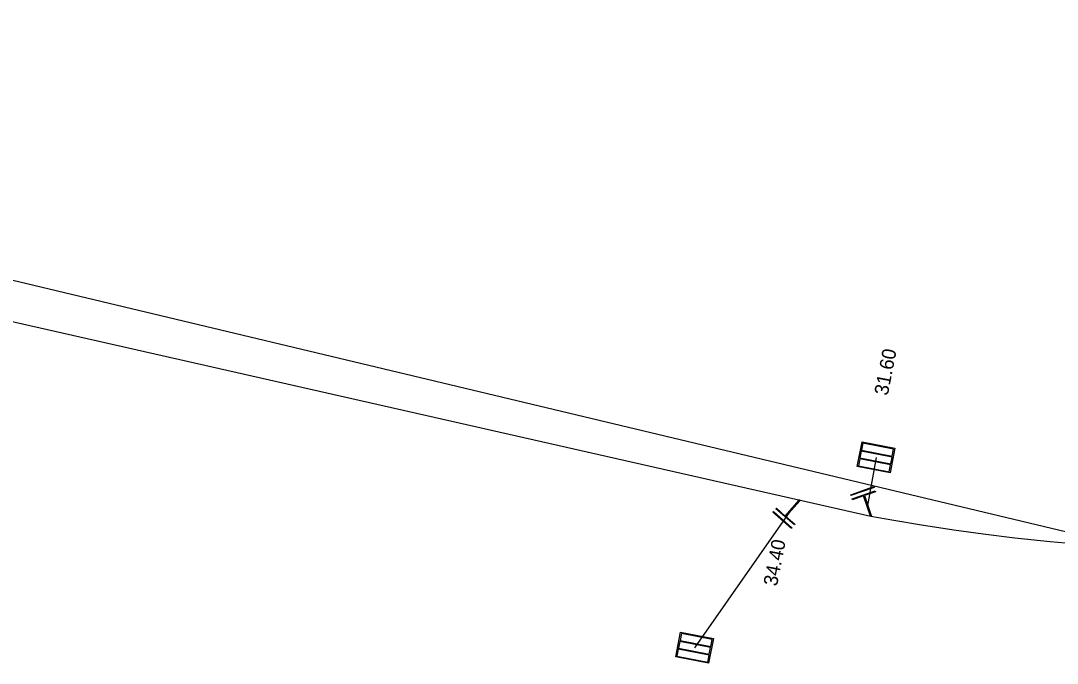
# Model space of a CAD drawing. Extents: x -817726 to -817387, y -1067947 to -1067694.
# Drawn here: x -817640.17 to -817603.04, y -1067814.67 to -1067791.65 of the extents above; entities that cross this region are included whole.
import ezdxf

# ---------------------------------------------------------------- set-up
doc = ezdxf.new("R2010")
doc.units = 0
doc.layers.add('Default', color=7, linetype='Continuous')
doc.layers.add('Level 0', color=7, linetype='Continuous')

msp = doc.modelspace()

# ---------------------------------------------------------------- linework, layer by layer
at = {"layer": 'Default'}
for points in [[(-817610.031, -1067806.741), (-817608.853, -1067806.969), (-817609.025, -1067807.854), (-817610.203, -1067807.625), (-817610.031, -1067806.741)], [(-817610.05, -1067807.033), (-817608.946, -1067807.247), (-817608.897, -1067806.999), (-817610.002, -1067806.784), (-817610.05, -1067807.033)], [(-817610.111, -1067807.349), (-817610.159, -1067807.595), (-817609.055, -1067807.81), (-817609.007, -1067807.564), (-817610.111, -1067807.349)], [(-817610.057, -1067807.07), (-817610.104, -1067807.312), (-817609, -1067807.527), (-817608.953, -1067807.284), (-817610.057, -1067807.07)], [(-817610.427, -1067808.659), (-817610.437, -1067808.632), (-817609.607, -1067808.345), (-817609.597, -1067808.372), (-817610.427, -1067808.659)], [(-817609.705, -1067809.402), (-817609.725, -1067809.398), (-817609.975, -1067808.674), (-817610.375, -1067808.812), (-817610.385, -1067808.783), (-817609.554, -1067808.497), (-817609.545, -1067808.526), (-817609.947, -1067808.664), (-817609.7, -1067809.378), (-817609.705, -1067809.402)], [(-817612.26, -1067808.847), (-817612.755, -1067809.416), (-817612.435, -1067809.695), (-817612.454, -1067809.718), (-817613.117, -1067809.142), (-817613.097, -1067809.119), (-817612.779, -1067809.397), (-817612.275, -1067808.819), (-817612.255, -1067808.823), (-817612.26, -1067808.847)], [(-817612.541, -1067809.818), (-817612.56, -1067809.839), (-817613.223, -1067809.263), (-817613.203, -1067809.241), (-817612.541, -1067809.818)], [(-817616.532, -1067813.562), (-817615.354, -1067813.79), (-817615.526, -1067814.675), (-817616.704, -1067814.446), (-817616.532, -1067813.562)], [(-817616.551, -1067813.854), (-817615.447, -1067814.068), (-817615.398, -1067813.82), (-817616.503, -1067813.605), (-817616.551, -1067813.854)], [(-817616.558, -1067813.891), (-817616.605, -1067814.133), (-817615.501, -1067814.348), (-817615.454, -1067814.105), (-817616.558, -1067813.891)], [(-817616.612, -1067814.17), (-817616.66, -1067814.416), (-817615.556, -1067814.631), (-817615.508, -1067814.385), (-817616.612, -1067814.17)]]:
    msp.add_lwpolyline(points, dxfattribs=at)
at = {"layer": 'Level 0'}
for p, q in [((-817687.989, -1067791.646), (-817609.709, -1067809.401)), ((-817600.744, -1067810.444), (-817655.428, -1067797.384)), ((-817609.522, -1067807.302), (-817609.832, -1067809.02)), ((-817612.52, -1067809.119), (-817612.26, -1067808.821)), ((-817616.023, -1067814.123), (-817612.52, -1067809.119)), ((-817609.832, -1067809.02), (-817609.708, -1067809.4)), ((-817609.709, -1067809.401), (-817608.896, -1067809.548)), ((-817608.896, -1067809.548), (-817607.901, -1067809.715)), ((-817607.901, -1067809.715), (-817606.739, -1067809.893)), ((-817606.739, -1067809.893), (-817605.689, -1067810.037)), ((-817605.689, -1067810.037), (-817604.554, -1067810.175)), ((-817604.554, -1067810.175), (-817603.291, -1067810.307)), ((-817603.291, -1067810.307), (-817602.123, -1067810.41))]:
    msp.add_line(p, q, dxfattribs=at)

# ---------------------------------------------------------------- texts
for s, p in [('31.60', (-817609.108, -1067805.099)), ('34.40', (-817613.079, -1067811.935))]:
    msp.add_text(s, height=0.5, rotation=79, dxfattribs=at).set_placement(p)

doc.saveas('drawing.dxf')
